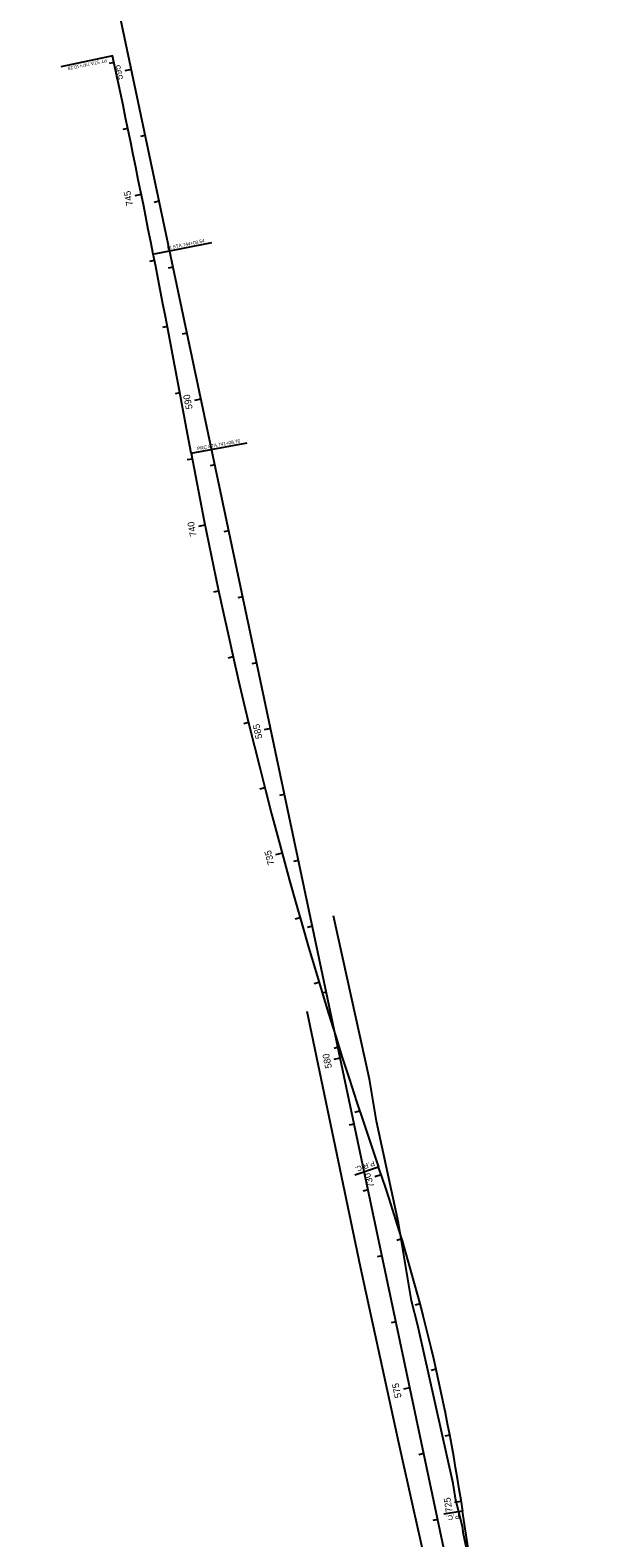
# Model space of a CAD drawing. Extents: x 2003883 to 2008298, y 399149 to 424047.
# Drawn here: x 2005094 to 2005922, y 404625 to 406863 of the extents above; entities that cross this region are included whole.
import ezdxf

# ---------------------------------------------------------------- set-up
doc = ezdxf.new("R2010")
doc.units = 0
for name, color, linetype in [('BaselineSurvey', 7, 'Continuous'), ('BaselineTextWt2', 7, 'Continuous'), ('RWLine_ep', 7, 'Continuous')]:
    doc.layers.add(name, color=color, linetype=linetype)

msp = doc.modelspace()

# ---------------------------------------------------------------- linework, layer by layer
at = {"layer": 'BaselineSurvey'}
for p, q in [((2005921.5, 403604.6), (2005094.5, 407516.1)), ((2005219.2, 406815), (2005211.8, 406813.4)), ((2005244.9, 406804.6), (2005235.1, 406802.5)), ((2005239.6, 406717.1), (2005232.3, 406715.5)), ((2005265.6, 406706.7), (2005258.3, 406705.2)), ((2005259.6, 406619.1), (2005249.8, 406617.1)), ((2005286.3, 406608.9), (2005278.9, 406607.3)), ((2005279.2, 406521), (2005271.8, 406519.6)), ((2005307, 406511), (2005299.6, 406509.5)), ((2005298.3, 406422.9), (2005291, 406421.4)), ((2005327.7, 406413.2), (2005320.3, 406411.7)), ((2005317, 406324.6), (2005309.7, 406323.2)), ((2005348.3, 406315.4), (2005338.6, 406313.3)), ((2005335.3, 406226.3), (2005328, 406225)), ((2005369, 406217.5), (2005361.7, 406216)), ((2005354.2, 406128.1), (2005344.4, 406126.2)), ((2005389.7, 406119.7), (2005382.4, 406118.1)), ((2005374.5, 406030.2), (2005367.1, 406028.6)), ((2005410.4, 406021.9), (2005403.1, 406020.3)), ((2005396.1, 405932.6), (2005388.7, 405930.9)), ((2005431.1, 405924), (2005423.8, 405922.5)), ((2005419, 405835.2), (2005411.7, 405833.4)), ((2005451.8, 405826.2), (2005442, 405824.1)), ((2005443.2, 405738.2), (2005435.9, 405736.3)), ((2005472.5, 405728.4), (2005465.1, 405726.8)), ((2005468.7, 405641.5), (2005459.1, 405638.9)), ((2005493.2, 405630.5), (2005485.8, 405629)), ((2005495.6, 405545.2), (2005488.4, 405543.1)), ((2005513.8, 405532.7), (2005506.5, 405531.1)), ((2005523.8, 405449.2), (2005516.6, 405447.1)), ((2005534.5, 405434.8), (2005527.2, 405433.3)), ((2005553.2, 405353.7), (2005546.1, 405351.4)), ((2005555.2, 405337), (2005545.4, 405334.9)), ((2005584, 405258.5), (2005576.9, 405256.2)), ((2005575.9, 405239.2), (2005568.6, 405237.6)), ((2005616.1, 405163.8), (2005606.6, 405160.6)), ((2005596.6, 405141.3), (2005589.2, 405139.8)), ((2005646.6, 405068.6), (2005639.4, 405066.4)), ((2005617.3, 405043.5), (2005609.9, 405041.9)), ((2005673.7, 404972.3), (2005666.5, 404970.4)), ((2005638, 404945.7), (2005630.6, 404944.1)), ((2005697.5, 404875.2), (2005690.2, 404873.6)), ((2005658.6, 404847.8), (2005648.9, 404845.8)), ((2005717.9, 404777.3), (2005710.5, 404775.9)), ((2005679.3, 404750), (2005672, 404748.4)), ((2005734.8, 404678.8), (2005725, 404677.3)), ((2005700, 404652.1), (2005692.7, 404650.6)), ((2005779.8, 404377.3), (2005737, 404664.5))]:
    msp.add_line(p, q, dxfattribs=at)
for centre, radius, start, end in [((1982794.8, 402084), 22918, 10.43499, 11.93881), ((2012544.2, 407562.8), 7331.7, 190.43499, 199.00412), ((2002903.3, 404242.4), 2865, 8.4719, 19.0041)]:
    msp.add_arc(centre, radius, start, end, dxfattribs=at)
at = {"layer": 'BaselineTextWt2'}
for p, q in [((2005217.1, 406825), (2005139.9, 406808.7)), ((2005279.3, 406530.7), (2005364.4, 406547.6)), ((2005333.8, 406234.9), (2005417, 406250.3)), ((2005612.1, 405175.4), (2005576.9, 405163.3)), ((2005737, 404664.5), (2005708.8, 404660.3))]:
    msp.add_line(p, q, dxfattribs=at)
at = {"layer": 'RWLine_ep'}
for p, q in [((2005598.4, 405305.9), (2005545.2, 405548.1)), ((2005585.1, 405027.4), (2005506.2, 405406.3)), ((2005609.1, 405243.3), (2005598.4, 405305.9)), ((2005641.7, 405092.5), (2005609.1, 405243.3)), ((2005661.1, 404976.9), (2005641.7, 405092.5)), ((2005598.4, 404966.1), (2005585.1, 405027.4)), ((2005642.3, 404766), (2005598.4, 404966.1)), ((2005670.3, 404940.3), (2005661.1, 404976.9)), ((2005722.7, 404705.6), (2005670.3, 404940.3)), ((2005664.6, 404665.8), (2005642.3, 404766)), ((2005726.8, 404681.1), (2005722.7, 404705.6)), ((2005737, 404641.9), (2005726.8, 404681.1)), ((2005679.9, 404597.8), (2005664.6, 404665.8)), ((2005738.2, 404630.3), (2005737, 404641.9)), ((2005745, 404598.3), (2005738.2, 404630.3))]:
    msp.add_line(p, q, dxfattribs=at)

# ---------------------------------------------------------------- texts
at = {"layer": 'BaselineTextWt2'}
for s, height, rotation, p in [('PT STA.747+10.28', 5, 191.9388, (2005207.8, 406820.5)), ('595', 10, 101.9389, (2005232.6, 406790.3)), ('745', 10, 101.4131, (2005247.5, 406603.3)), ('PI STA.744+09.54', 5, 11.1869, (2005298.4, 406537.1)), ('590', 10, 101.9389, (2005336, 406301.2)), ('PRC STA.741+08.76', 5, 10.435, (2005343.1, 406239.2)), ('740', 10, 101.285, (2005342.1, 406112.2)), ('585', 10, 101.9389, (2005439.5, 405812)), ('735', 10, 105.1924, (2005457.7, 405624.9)), ('580', 10, 101.9389, (2005542.9, 405322.8)), ('P.R.C.', 7.5, 199.0041, (2005604.8, 405184.8)), ('730', 10, 108.7593, (2005606.1, 405146.5)), ('575', 10, 101.9389, (2005646.3, 404833.6)), ('725', 10, 98.76, (2005722, 404663.5)), ('P.C.', 7.5, 188.4719, (2005731.7, 404660.9))]:
    msp.add_text(s, height=height, rotation=rotation, dxfattribs=at).set_placement(p)

doc.saveas('drawing.dxf')
